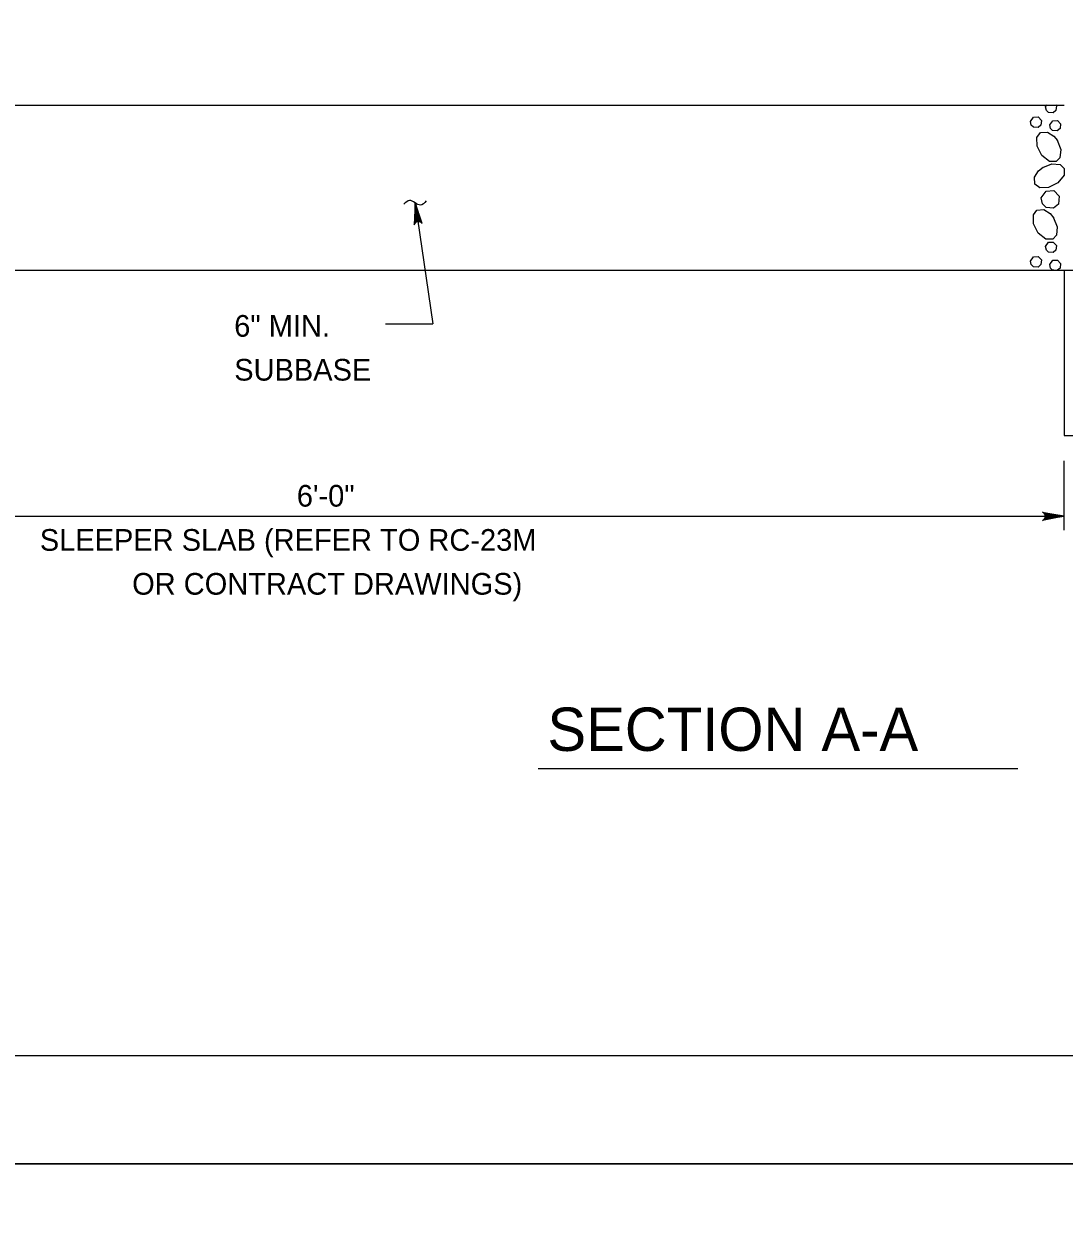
# Model space of a CAD drawing. Extents: x 2084213 to 2099800, y 976677 to 981262.
# Drawn here: x 2094781 to 2095252, y 978601 to 979143 of the extents above; entities that cross this region are included whole.
import ezdxf

# ---------------------------------------------------------------- set-up
doc = ezdxf.new("R2010")
doc.units = 0
doc.layers.add('1', color=7, linetype='Continuous')
doc.layers.add('PLT-BNDY', color=7, linetype='Continuous')

msp = doc.modelspace()

# ---------------------------------------------------------------- linework, layer by layer
at = {"layer": '1'}
for p, q in [((2094652.37, 979106.66), (2095252.37, 979106.66)), ((2094957.96, 979062.29), (2094966.08, 979007.41)), ((2094602.37, 979031.66), (2095302.37, 979031.66)), ((2095252.37, 979031.66), (2095252.37, 978956.66)), ((2094944.49, 979007.41), (2094966.08, 979007.41)), ((2095252.37, 978956.66), (2095352.37, 978956.66)), ((2095252.37, 978913.67), (2095252.37, 978945.2)), ((2094503.83, 978919.99), (2095252.37, 978919.99)), ((2095013.83, 978805.59), (2095231.42, 978805.59))]:
    msp.add_line(p, q, dxfattribs=at)
for points in [[(2096781.61, 978675.28), (2096781.61, 980525.68), (2094202.86, 980525.68), (2094202.86, 978675.28), (2096781.61, 978675.28), (2096781.61, 978761.76), (2096125.44, 978761.76), (2096125.44, 978973.96), (2096781.61, 978973.96), (2096781.61, 979068.98), (2096125.44, 979068.98), (2096125.44, 978675.28), (2096383.97, 978675.28), (2096383.97, 978761.76), (2096383.97, 978675.28), (2096636.6, 978675.28), (2096636.6, 978761.76), (2096636.6, 978721.35), (2096781.61, 978721.35)], [(2095244.01, 979105.84), (2095244.59, 979106.67)], [(2095248.58, 979106.67), (2095248.92, 979106.32), (2095248.7, 979104.19), (2095247.4, 979103.1), (2095245.31, 979103.25), (2095244.33, 979104.2), (2095244.01, 979105.84)], [(2095237.18, 979099.22), (2095238.51, 979101.1), (2095240.62, 979101.22), (2095242.09, 979099.7), (2095241.88, 979097.57), (2095240.57, 979096.48), (2095238.48, 979096.63), (2095237.5, 979097.58), (2095237.18, 979099.22)], [(2095245.87, 979097.67), (2095247.19, 979099.55), (2095249.31, 979099.67), (2095250.78, 979098.15), (2095250.56, 979096.02), (2095249.26, 979094.93), (2095247.17, 979095.08), (2095246.19, 979096.03), (2095245.87, 979097.67)], [(2095249.2, 979090.67), (2095250.84, 979086.54), (2095250.51, 979082.75), (2095248.8, 979080.95), (2095245.72, 979081.01), (2095242.23, 979083.74), (2095240.12, 979087.97), (2095240.05, 979091.95), (2095241.64, 979094.19), (2095244.81, 979094.4), (2095247.65, 979092.59), (2095249.31, 979090.5)], [(2095242.66, 979078.3), (2095246.79, 979079.93), (2095250.58, 979079.61), (2095252.38, 979077.89), (2095252.33, 979074.82), (2095249.59, 979071.32), (2095245.37, 979069.21), (2095241.38, 979069.14), (2095239.14, 979070.73), (2095238.93, 979073.9), (2095240.75, 979076.74), (2095242.83, 979078.4)], [(2095242, 979064.48), (2095244.2, 979067.61), (2095247.72, 979067.81), (2095250.17, 979065.28), (2095249.82, 979061.72), (2095247.64, 979059.91), (2095244.17, 979060.16), (2095242.53, 979061.75), (2095242, 979064.47)], [(2094957.96, 979062.29), (2094957.58, 979052.34), (2094957.79, 979052.75), (2094957.99, 979053.16), (2094958.28, 979053.4), (2094958.58, 979053.64), (2094958.9, 979053.75), (2094959.21, 979053.85), (2094959.55, 979053.84), (2094959.88, 979053.83), (2094960.23, 979053.69), (2094960.59, 979053.55), (2094960.9, 979053.21), (2094961.21, 979052.88), (2094957.96, 979062.29), (2094960.9, 979053.21), (2094960.59, 979053.55), (2094957.96, 979062.29), (2094960.23, 979053.69), (2094959.88, 979053.83), (2094957.96, 979062.29), (2094959.55, 979053.84), (2094959.21, 979053.85), (2094957.96, 979062.29), (2094958.9, 979053.75), (2094958.58, 979053.64), (2094957.96, 979062.29), (2094958.28, 979053.4), (2094957.99, 979053.16), (2094957.96, 979062.29), (2094957.79, 979052.75)], [(2095247.6, 979055.46), (2095249.24, 979051.33), (2095248.91, 979047.54), (2095247.2, 979045.74), (2095244.13, 979045.8), (2095240.63, 979048.53), (2095238.52, 979052.76), (2095238.45, 979056.74), (2095240.04, 979058.98), (2095243.21, 979059.19), (2095246.05, 979057.37), (2095247.71, 979055.29)], [(2095244.01, 979042.47), (2095245.33, 979044.35), (2095247.45, 979044.48), (2095248.92, 979042.95), (2095248.7, 979040.82), (2095247.4, 979039.73), (2095245.31, 979039.88), (2095244.33, 979040.83), (2095244.01, 979042.47)], [(2095237.18, 979035.85), (2095238.51, 979037.73), (2095240.62, 979037.86), (2095242.09, 979036.33), (2095241.88, 979034.2), (2095240.57, 979033.11), (2095238.48, 979033.26), (2095237.5, 979034.22), (2095237.18, 979035.85)], [(2095245.87, 979034.3), (2095247.19, 979036.18), (2095249.31, 979036.3), (2095250.78, 979034.78), (2095250.56, 979032.65), (2095249.39, 979031.67)], [(2095247.79, 979031.67), (2095247.17, 979031.71), (2095246.19, 979032.66), (2095245.87, 979034.3)], [(2095252.37, 978919.99), (2095242.59, 978918.15), (2095242.96, 978918.41), (2095243.34, 978918.68), (2095243.53, 978919), (2095243.73, 978919.33), (2095243.78, 978919.66), (2095243.84, 978919.99), (2095243.78, 978920.32), (2095243.73, 978920.64), (2095243.53, 978920.97), (2095243.34, 978921.3), (2095242.96, 978921.56), (2095242.59, 978921.82), (2095252.37, 978919.99), (2095242.96, 978921.56), (2095243.34, 978921.3), (2095252.37, 978919.99), (2095243.53, 978920.97), (2095243.73, 978920.64), (2095252.37, 978919.99), (2095243.78, 978920.32), (2095243.84, 978919.99), (2095252.37, 978919.99), (2095243.78, 978919.66), (2095243.73, 978919.33), (2095252.37, 978919.99), (2095243.53, 978919), (2095243.34, 978918.68), (2095252.37, 978919.99), (2095242.96, 978918.41)]]:
    msp.add_lwpolyline(points, dxfattribs=at)
msp.add_spline([(2094963.01, 979063.14), (2094960.43, 979061.23), (2094955.47, 979063.36), (2094952.91, 979061.61)], degree=3, dxfattribs=at)
at = {"layer": 'PLT-BNDY'}
for points in [[(2094074.91, 980574.89), (2096834.1, 980574.89), (2096834.1, 978626.07), (2094074.91, 978626.07)], [(2094074.91, 978626.07), (2096834.1, 978626.07), (2096834.1, 976677.25), (2094074.91, 976677.25)]]:
    msp.add_lwpolyline(points, close=True, dxfattribs=at)

# ---------------------------------------------------------------- texts
at = {"layer": '1'}
for s, height, p in [('6" MIN.', 9.843, (2094875.93, 979001.5)), ('SUBBASE', 9.843, (2094875.93, 978981.58)), ('6\'-0"', 9.843, (2094904.33, 978924.38)), ('SLEEPER SLAB (REFER TO RC-23M', 9.8425, (2094787.75, 978904.34)), ('OR CONTRACT DRAWINGS)', 9.8425, (2094829.64, 978884.42)), ('SECTION A-A', 19.685, (2095018, 978813.51))]:
    msp.add_text(s, height=height, dxfattribs=at).set_placement(p)

doc.saveas('drawing.dxf')
